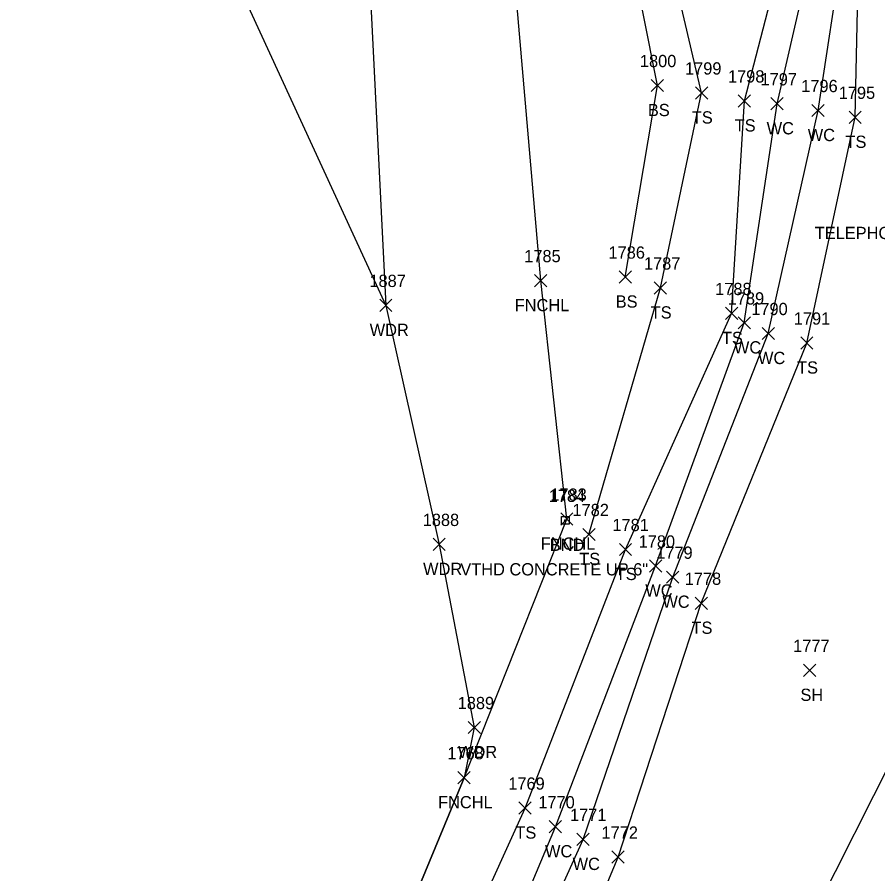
# Model space of a CAD drawing. Extents: x 1623612 to 1625808, y 621345 to 627748.
# Drawn here: x 1624481.9 to 1624622.4, y 626193.8 to 626333.7 of the extents above; entities that cross this region are included whole.
import ezdxf

# ---------------------------------------------------------------- set-up
doc = ezdxf.new("R2010")
doc.units = 0
for name, color, linetype in [('L_A', 7, 'Continuous'), ('L_I', 7, 'Continuous'), ('L_TIC', 7, 'Continuous'), ('LAWA', 7, 'Continuous'), ('LAWE', 7, 'Continuous'), ('LELB', 7, 'Continuous'), ('Level 18', 7, 'Continuous'), ('LFNC', 7, 'Continuous'), ('LSOGP', 7, 'Continuous'), ('M_A', 7, 'Continuous'), ('M_C', 7, 'Continuous'), ('M_I', 7, 'Continuous'), ('U_C', 7, 'Continuous')]:
    doc.layers.add(name, color=color, linetype=linetype)

msp = doc.modelspace()

# ---------------------------------------------------------------- linework, layer by layer
at = {"layer": 'L_TIC'}
for points in [[(1624585.45, 626321.54), (1624587.45, 626323.54)], [(1624587.45, 626321.54), (1624585.45, 626323.54)], [(1624592.66, 626320.33), (1624594.66, 626322.33)], [(1624594.66, 626320.33), (1624592.66, 626322.33)], [(1624599.66, 626319.03), (1624601.66, 626321.03)], [(1624601.66, 626319.03), (1624599.66, 626321.03)], [(1624604.98, 626318.56), (1624606.98, 626320.56)], [(1624606.98, 626318.56), (1624604.98, 626320.56)], [(1624611.69, 626317.46), (1624613.69, 626319.46)], [(1624613.69, 626317.46), (1624611.69, 626319.46)], [(1624617.75, 626316.35), (1624619.75, 626318.35)], [(1624619.75, 626316.35), (1624617.75, 626318.35)], [(1624566.39, 626289.68), (1624568.39, 626291.68)], [(1624568.39, 626289.68), (1624566.39, 626291.68)], [(1624580.2, 626290.26), (1624582.2, 626292.26)], [(1624582.2, 626290.26), (1624580.2, 626292.26)], [(1624585.94, 626288.48), (1624587.94, 626290.48)], [(1624587.94, 626288.48), (1624585.94, 626290.48)], [(1624541.1, 626285.63), (1624543.1, 626287.63)], [(1624543.1, 626285.63), (1624541.1, 626287.63)], [(1624597.57, 626284.31), (1624599.57, 626286.31)], [(1624599.57, 626284.31), (1624597.57, 626286.31)], [(1624599.64, 626282.77), (1624601.64, 626284.77)], [(1624601.64, 626282.77), (1624599.64, 626284.77)], [(1624603.56, 626281.04), (1624605.56, 626283.04)], [(1624605.56, 626281.04), (1624603.56, 626283.04)], [(1624609.85, 626279.48), (1624611.85, 626281.48)], [(1624611.85, 626279.48), (1624609.85, 626281.48)], [(1624570.65, 626250.72), (1624572.65, 626252.72)], [(1624572.65, 626250.72), (1624570.65, 626252.72)], [(1624574.27, 626248.21), (1624576.27, 626250.21)], [(1624576.27, 626248.21), (1624574.27, 626250.21)], [(1624549.81, 626246.59), (1624551.81, 626248.59)], [(1624551.81, 626246.59), (1624549.81, 626248.59)], [(1624580.23, 626245.76), (1624582.23, 626247.76)], [(1624582.23, 626245.76), (1624580.23, 626247.76)], [(1624585.16, 626243.06), (1624587.16, 626245.06)], [(1624587.16, 626243.06), (1624585.16, 626245.06)], [(1624587.96, 626241.23), (1624589.96, 626243.23)], [(1624589.96, 626241.23), (1624587.96, 626243.23)], [(1624592.61, 626236.98), (1624594.61, 626238.98)], [(1624594.61, 626236.98), (1624592.61, 626238.98)], [(1624610.31, 626226.02), (1624612.31, 626228.02)], [(1624612.31, 626226.02), (1624610.31, 626228.02)], [(1624555.53, 626216.68), (1624557.53, 626218.68)], [(1624557.53, 626216.68), (1624555.53, 626218.68)], [(1624553.88, 626208.48), (1624555.88, 626210.48)], [(1624555.88, 626208.48), (1624553.88, 626210.48)], [(1624563.84, 626203.52), (1624565.84, 626205.52)], [(1624565.84, 626203.52), (1624563.84, 626205.52)], [(1624568.78, 626200.47), (1624570.78, 626202.47)], [(1624570.78, 626200.47), (1624568.78, 626202.47)], [(1624573.3, 626198.4), (1624575.3, 626200.4)], [(1624575.3, 626198.4), (1624573.3, 626200.4)], [(1624579.02, 626195.52), (1624581.02, 626197.52)], [(1624581.02, 626195.52), (1624579.02, 626197.52)]]:
    msp.add_lwpolyline(points, dxfattribs=at)
at = {"layer": 'LAWA'}
msp.add_lwpolyline([(1624490.09, 626423.2), (1624517.67, 626445.05), (1624533.77, 626405.17), (1624539.5, 626339.09), (1624542.1, 626286.63), (1624550.81, 626247.59), (1624556.53, 626217.68)], dxfattribs=at)
at = {"layer": 'LAWE'}
for points in [[(1624478.34, 625960.64), (1624502.51, 626006.49), (1624510.02, 626033.48), (1624538.01, 626022.07), (1624539, 626026.11), (1624515.37, 626039.01), (1624525.82, 626080.12), (1624541.49, 626122.12), (1624557.13, 626161.32), (1624574.3, 626199.4), (1624588.96, 626242.23), (1624604.56, 626282.04), (1624612.69, 626318.46), (1624618.16, 626354.23), (1624633.32, 626339.44), (1624651.01, 626315.35), (1624653.64, 626319.94), (1624637.21, 626339.9), (1624620.54, 626359.04), (1624606.22, 626380.55), (1624599.51, 626405.02), (1624601.1, 626417.17), (1624599.39, 626418.68), (1624597.72, 626417.92)], [(1624475.9, 625962), (1624495.4, 626010.74), (1624513.45, 626053.64), (1624523.83, 626080.72), (1624539.75, 626122.53), (1624554.03, 626163.77), (1624569.78, 626201.47), (1624586.16, 626244.06), (1624600.64, 626283.77), (1624605.98, 626319.56), (1624614.72, 626357.4), (1624602.68, 626377.24), (1624598.91, 626387.68), (1624595.49, 626400.19), (1624596.27, 626415.38)]]:
    msp.add_lwpolyline(points, dxfattribs=at)
at = {"layer": 'LELB'}
for points in [[(1624581.2, 626291.26), (1624586.45, 626322.54), (1624579.39, 626358.15), (1624571.75, 626385.33), (1624574.35, 626409.32), (1624582.94, 626412.25), (1624577.11, 626422.08), (1624565.06, 626445.8)], [(1624405.5, 625728.14), (1624428.24, 625773.19), (1624451.7, 625813.41), (1624479.3, 625869.39), (1624496.23, 625906.08), (1624514.91, 625948.11), (1624536.21, 625990.48), (1624546.45, 626029.66), (1624561.04, 626063.21), (1624576.65, 626110.9), (1624590.48, 626147.32), (1624609.26, 626181.73), (1624628.06, 626219.01), (1624648.51, 626267.43), (1624661.85, 626303.08), (1624661.36, 626343.87), (1624651.86, 626347.04), (1624650.32, 626353.64), (1624652.97, 626362.16), (1624638.4, 626383.22), (1624618.17, 626397.94), (1624604.09, 626415.44)], [(1624575.27, 626249.21), (1624586.94, 626289.48), (1624593.66, 626321.33), (1624578.11, 626387.68), (1624577.85, 626405.25)], [(1624375.32, 625803.31), (1624399.86, 625843.95), (1624436.39, 625893.65), (1624461.77, 625932.24), (1624474.24, 625964.36), (1624492.43, 626012.44), (1624506.84, 626058.35), (1624517.83, 626084.66), (1624533.25, 626127.2), (1624547.8, 626166.97), (1624564.84, 626204.52), (1624581.23, 626246.76), (1624598.57, 626285.31), (1624600.66, 626320.03), (1624610.19, 626356.83), (1624599.69, 626375.7), (1624596.69, 626386.19), (1624590.38, 626400.67)], [(1624474.79, 625911.16), (1624486.83, 625907.23), (1624489.26, 625914.69), (1624471.27, 625929.28), (1624479.84, 625959.91), (1624504.09, 626004.46), (1624515.23, 626027.37), (1624539.55, 626018.82), (1624542.04, 626026.15), (1624519.32, 626037.26), (1624532.33, 626078.05), (1624547.61, 626119.81), (1624564.25, 626158.84), (1624580.02, 626196.52), (1624593.61, 626237.98), (1624610.85, 626280.48), (1624618.75, 626317.35), (1624619.41, 626347.56)]]:
    msp.add_lwpolyline(points, dxfattribs=at)
at = {"layer": 'Level 18'}
msp.add_lwpolyline([(1624570.76, 626252.15), (1624572.01, 626252.15), (1624572.01, 626250.9), (1624570.76, 626250.9)], close=True, dxfattribs=at)
msp.add_circle((1624571.38, 626251.52), 0.0833, dxfattribs=at)
at = {"layer": 'LFNC'}
msp.add_lwpolyline([(1624427.61, 625937.89), (1624449.98, 625974.47), (1624478.22, 626020.43), (1624495.88, 626064.36), (1624506.11, 626090.08), (1624523, 626131.63), (1624538.15, 626169.09), (1624554.88, 626209.48), (1624571.65, 626251.72), (1624567.39, 626290.68), (1624562.31, 626349.95), (1624561.25, 626380.14), (1624560.31, 626420.97), (1624559.52, 626449.49)], dxfattribs=at)
at = {"layer": 'LSOGP'}
msp.add_lwpolyline([(1624514.57, 626346.5), (1624542.1, 626286.63), (1624550.81, 626247.59), (1624556.53, 626217.68), (1624554.88, 626209.48), (1624538.15, 626169.09), (1624523, 626131.63), (1624506.11, 626090.08)], dxfattribs=at)

# ---------------------------------------------------------------- texts
at = {"layer": 'L_A'}
for s, p in [('BS', (1624584.89, 626317.54)), ('TS', (1624592.07, 626316.33)), ('TS', (1624599.07, 626315.03)), ('WC', (1624604.29, 626314.56)), ('WC', (1624611, 626313.46)), ('TS', (1624617.16, 626312.35)), ('FNCHL', (1624563.14, 626285.68)), ('BS', (1624579.64, 626286.26)), ('TS', (1624585.35, 626284.48)), ('WDR', (1624539.46, 626281.63)), ('TS', (1624596.98, 626280.31)), ('WC', (1624598.94, 626278.77)), ('WC', (1624602.87, 626277.04)), ('TS', (1624609.26, 626275.48)), ('FNCHL', (1624567.4, 626246.72)), ('TS', (1624573.68, 626244.21)), ('WDR', (1624548.18, 626242.59)), ('TS', (1624579.64, 626241.76)), ('WC', (1624584.47, 626239.06)), ('WC', (1624587.26, 626237.23)), ('TS', (1624592.02, 626232.98)), ('SH', (1624609.8, 626222.02)), ('WDR', (1624553.89, 626212.68)), ('FNCHL', (1624550.63, 626204.48)), ('TS', (1624563.25, 626199.52)), ('WC', (1624568.09, 626196.47)), ('WC', (1624572.6, 626194.4))]:
    msp.add_text(s, height=2, dxfattribs=at).set_placement(p)
at = {"layer": 'L_I'}
for s, p in [('1800', (1624583.59, 626325.54)), ('1799', (1624590.96, 626324.33)), ('1798', (1624597.97, 626323.03)), ('1797', (1624603.29, 626322.56)), ('1796', (1624609.94, 626321.46)), ('1795', (1624616.06, 626320.35)), ('1785', (1624564.7, 626293.68)), ('1786', (1624578.46, 626294.26)), ('1787', (1624584.25, 626292.48)), ('1887', (1624539.41, 626289.63)), ('1788', (1624595.88, 626288.31)), ('1789', (1624597.93, 626286.77)), ('1790', (1624601.78, 626285.04)), ('1791', (1624608.72, 626283.48)), ('1783', (1624568.96, 626254.72)), ('1782', (1624572.58, 626252.21)), ('1888', (1624548.12, 626250.59)), ('1781', (1624579.1, 626249.76)), ('1780', (1624583.38, 626247.06)), ('1779', (1624586.25, 626245.23)), ('1778', (1624590.91, 626240.98)), ('1777', (1624608.62, 626230.02)), ('1889', (1624553.83, 626220.68)), ('1768', (1624552.14, 626212.48)), ('1769', (1624562.09, 626207.52)), ('1770', (1624567, 626204.47)), ('1771', (1624572.17, 626202.4)), ('1772', (1624577.32, 626199.52))]:
    msp.add_text(s, height=2, dxfattribs=at).set_placement(p)
at = {"layer": 'M_A'}
msp.add_text('BND', height=2, dxfattribs=at).set_placement((1624568.87, 626246.52))
at = {"layer": 'M_C'}
msp.add_text('VTHD CONCRETE UP 6"', height=2, dxfattribs=at).set_placement((1624554.26, 626242.52))
at = {"layer": 'M_I'}
msp.add_text('1784', height=2, dxfattribs=at).set_placement((1624568.69, 626254.52))
at = {"layer": 'U_C'}
msp.add_text('TELEPHONE JUNCTION BOX', height=2, dxfattribs=at).set_placement((1624612.15, 626297.46))

doc.saveas('drawing.dxf')
